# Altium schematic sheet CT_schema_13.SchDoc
size 387 x 278 mm
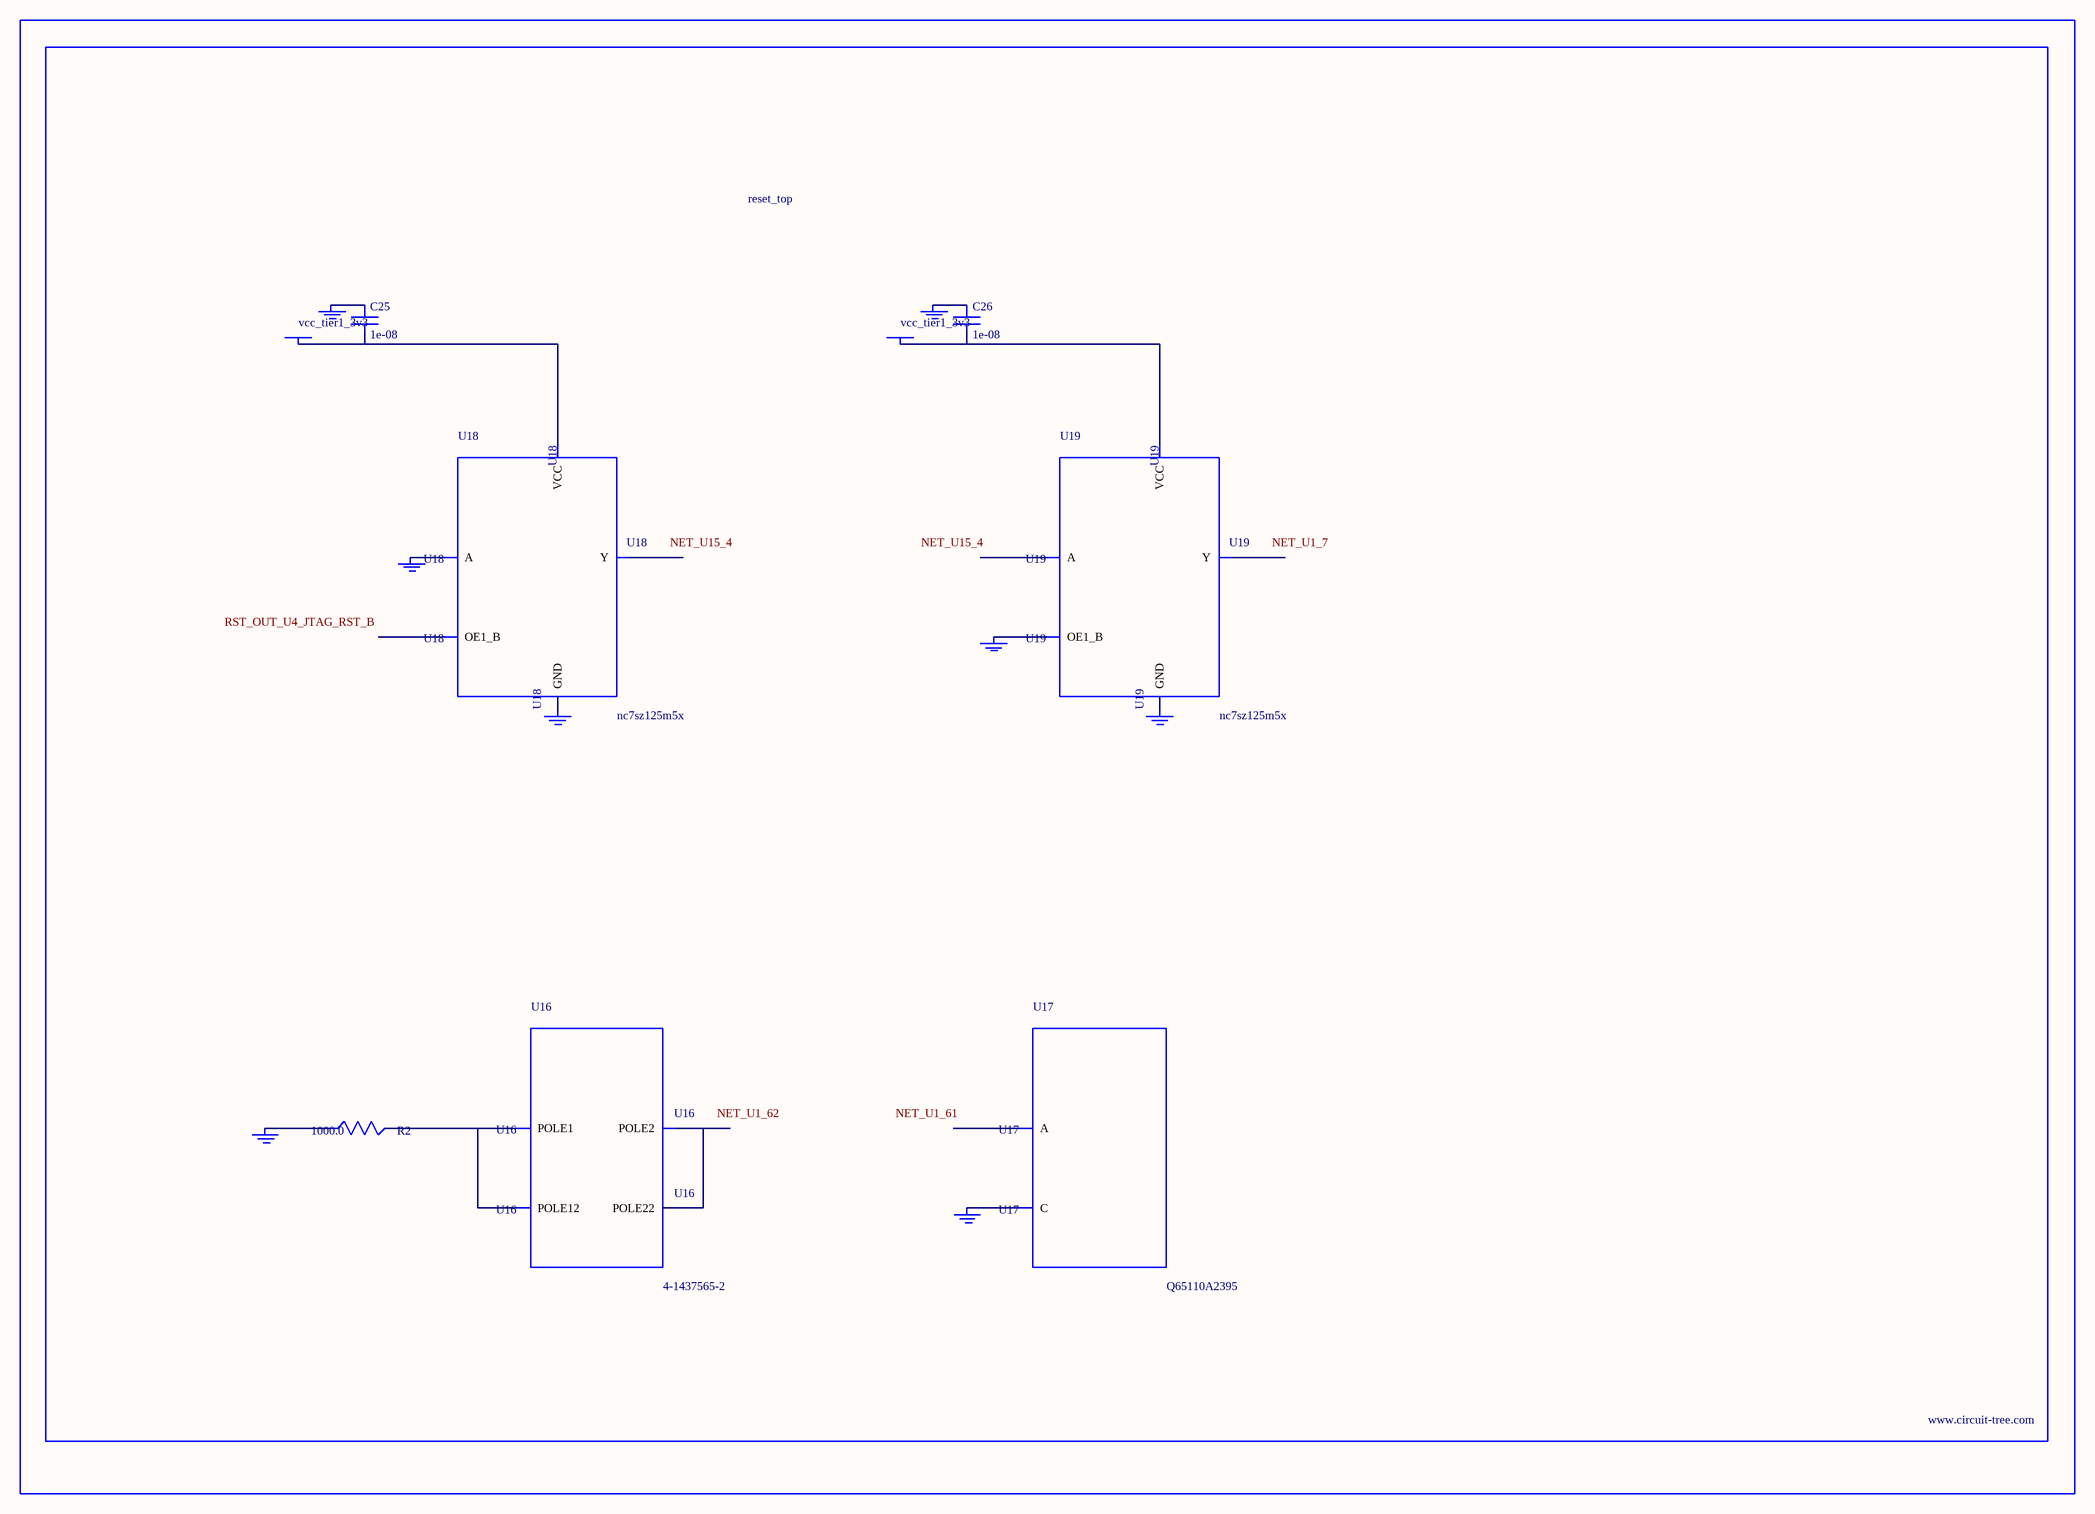
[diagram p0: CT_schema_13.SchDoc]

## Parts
BORDER12  (no value)
C25  1e-08  [C0402]
C26  1e-08  [C0402]
GND_INSTANCE_12_0  (no value)
GND_INSTANCE_12_1  (no value)
GND_INSTANCE_12_2  (no value)
GND_INSTANCE_12_3  (no value)
GND_INSTANCE_12_4  (no value)
GND_INSTANCE_12_5  (no value)
GND_INSTANCE_12_6  (no value)
GND_INSTANCE_12_7  (no value)
POWER_INSTANCE_12_0  vcc_tier1_3v3
POWER_INSTANCE_12_1  vcc_tier1_3v3
R2  1000.0  [R0603]
U16  4-1437565-2  [SW_4-1437565-2]
U17  Q65110A2395  [LGM67K-G1J2-24-Z]
U18  nc7sz125m5x  [NC7SZ125M5X]
U19  nc7sz125m5x  [NC7SZ125M5X]

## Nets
NetC25_1: C25.1 GND_INSTANCE_12_2.0(GND)
NetC25_2: C25.2 POWER_INSTANCE_12_0.0(PWR) U18.5(VCC)
NetC26_1: C26.1 GND_INSTANCE_12_5.0(GND)
NetC26_2: C26.2 POWER_INSTANCE_12_1.0(PWR) U19.5(VCC)
NetGND_INSTANCE_12_0_0: GND_INSTANCE_12_0.0(GND) R2.1
NetGND_INSTANCE_12_1_0: GND_INSTANCE_12_1.0(GND) U17.C
NetGND_INSTANCE_12_3_0: GND_INSTANCE_12_3.0(GND) U18.2(A)
NetGND_INSTANCE_12_4_0: GND_INSTANCE_12_4.0(GND) U18.3(GND)
NetGND_INSTANCE_12_6_0: GND_INSTANCE_12_6.0(GND) U19.1(OE1_B)
NetGND_INSTANCE_12_7_0: GND_INSTANCE_12_7.0(GND) U19.3(GND)
NetR2_2: R2.2 U16.1(POLE1) U16.2(POLE12)
NetU16_3: U16.3(POLE2) U16.4(POLE22)

Not connected (* = marked no-connect by the designer): U17 A; U18 1(OE1_B) 4(Y); U19 2(A) 4(Y)

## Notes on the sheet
- Labels drawn without touching a wire or pin: NET_U1_7, NET_U1_61, NET_U1_62, NET_U15_4, RST_OUT_U4_JTAG_RST_B

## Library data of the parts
BORDER12 = BORDER_PAGE12
C25 C26 = C0402C103K3RAC
GND_INSTANCE_12_0-GND_INSTANCE_12_7 = GND
POWER_INSTANCE_12_0 POWER_INSTANCE_12_1 = PWR
R2 = RC0603JR-071KL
